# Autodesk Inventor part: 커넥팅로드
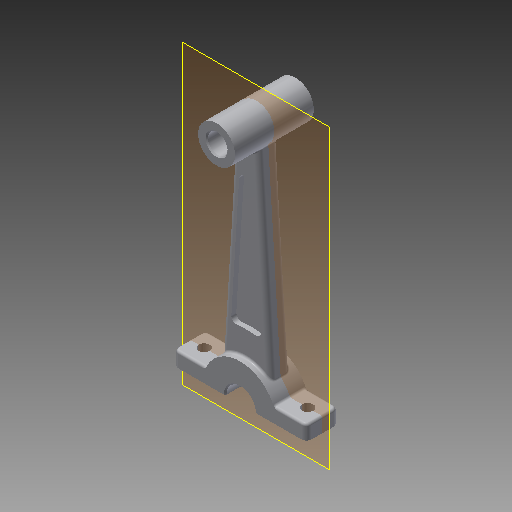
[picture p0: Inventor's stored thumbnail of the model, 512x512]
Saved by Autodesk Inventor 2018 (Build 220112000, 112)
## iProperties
Created: 2016-11
Part Number: 커넥팅로드
Material: 알루미늄 6061
Document SubType Name: Modeling
Designer: mduedu
Density: 2.71 g/cm^3
Mass: 44.549 g
Surface Area: 86.7069 cm^2
Volume: 16.4387 cm^3
Appearance: 알루미늄 - 평지
Author: mduedu
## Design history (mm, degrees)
sketch "스케치1" dims "d0" = 30, "d3" = 15
  geometry: L1 (0, 0)-(0, 96); L2 (-5, 90.41)-(-10, 11.18); L3 (5, 90.41)-(10, 11.18); C1 r 6 at (0, 0); C2 r 4 at (0, 96); 3 further points
  constraints: 6 end point, 4 coincident, 2 centre point, 2 symmetric about line, 1 vertical, 6 other
  dimensions: "d1" = 12 diameter of C1; "d2" = 8 diameter of C2; "d4" = 96 distance of L1.start L1.end; "d6" = 10 distance from line of L1 L2.end; "d7" = 5 distance from line of L1 L2.start
extrude "돌출1" new body sketch "스케치1" stored distance "d8" = 13; taper "d9" = 0 deg
extrude "돌출2" join sketch "스케치1" stored distance "d10" = 32; taper "d11" = 0 deg
sketch "스케치2"
  geometry: L1 (5, 90.41)-(10, 11.18) reference; L2 (-5, 90.41)-(-10, 11.18) reference; A1 r 7.5 centre (0, 96) between (5, 90.41) and (-5, 90.41) reference; A2 r 15 centre (0, 0) between (10, 11.18) and (-10, 11.18) reference
extrude "돌출3" join sketch "스케치2" stored distance "d12" = 8; taper "d13" = 0 deg
sketch "스케치3"
  geometry: L1 (-2.732, 78.715)-(-6.171, 24.226); L2 (2.732, 78.715)-(6.171, 24.226); L3 (0, 78.5)-(0, 25); A1 r 17.5 centre (0, 96) between (-2.732, 78.715) and (2.732, 78.715); A2 r 25 centre (0, 0) between (6.171, 24.226) and (-6.171, 24.226); 9 further points; 2 other entities
  constraints: 6 end point, 6 point on circle, 2 centre point, 1 symmetric about line, 1 vertical alignment, 6 other
  dimensions: "d18" = 10 dimension on A1; "d19" = 10 dimension on A2; "d20" = 3 dimension on L1
extrude "돌출4" cut sketch "스케치3" distance "d21" = 2; taper "d22" = 0 deg
fillet "모깎기1" dims "d23" = 2
fillet "모깎기2" dims "d24" = 2
fillet "모깎기3" dims "d25" = 1
chamfer "모따기1" distance "d26" = 0.5; stored, may be unused: second distance "d27" = 2, angle "d28" = 45 deg
sketch "스케치4"
  geometry: L1 (-27, -6)-(-13.748, -6); L2 (27, -6)-(27, 6); L3 (27, 6)-(13.748, 6); L4 (-27, 6)-(-27, -6); L5 (-27, -6)-(27, 6); L6 (27, -6)-(-27, 6); L7 (-13.748, 6)-(-27, 6); L8 (13.748, 6)-(-13.748, 6); L9 (13.748, -6)-(27, -6); L10 (-13.748, -6)-(13.748, -6); A1 r 15 centre (0, 0) between (-13.748, 6) and (13.748, 6) reference; 1 further point
  constraints: 20 end point, 10 parallel, 4 point on circle, 3 horizontal, 3 perpendicular, 2 midpoint
  dimensions: "d29" = 54 distance of L1.start L2.start; "d31" = 12 distance of L2.start L2.end
extrude "돌출5" join sketch "스케치4" stored distance "d32" = 0; taper "d33" = 0 deg
fillet "모깎기4" dims "d34" = 2
fillet "모깎기5" dims "d35" = 1
fillet "모깎기6" dims "d36" = 1
sketch "스케치5"
  geometry: L1 (1, 0)-(1, 9) reference; L2 (-18.5, 20.5)-(-33.5, 20.5) reference; L3 (-33.5, -11.5)-(-18.5, -11.5) reference; L4 (-26, 20.5)-(-26, -11.5); 3 further points
  constraints: 2 end point, 2 midpoint, 1 horizontal alignment, 1 symmetric about line
  dimensions: "d37" = 6 distance from line of point (-5, 4.5) L1
feature "분할1"
sketch "스케치7"
  geometry: 2 further points
  constraints: 2 other
hole "구멍2" sketch "스케치7" at (-47, 4.5), (-5, 4.5) diameter "d45" = 4.5; stored, may be unused: countersink angle "d49" = 90 deg, drill point angle "d51" = 0 deg; dims "d46" = 6, "d47" = 4, "d48" = 2, "d50" = 8
node "솔리드1"
mirror "대칭1"
other parameters: "d16" = 4, "d17" = 4
